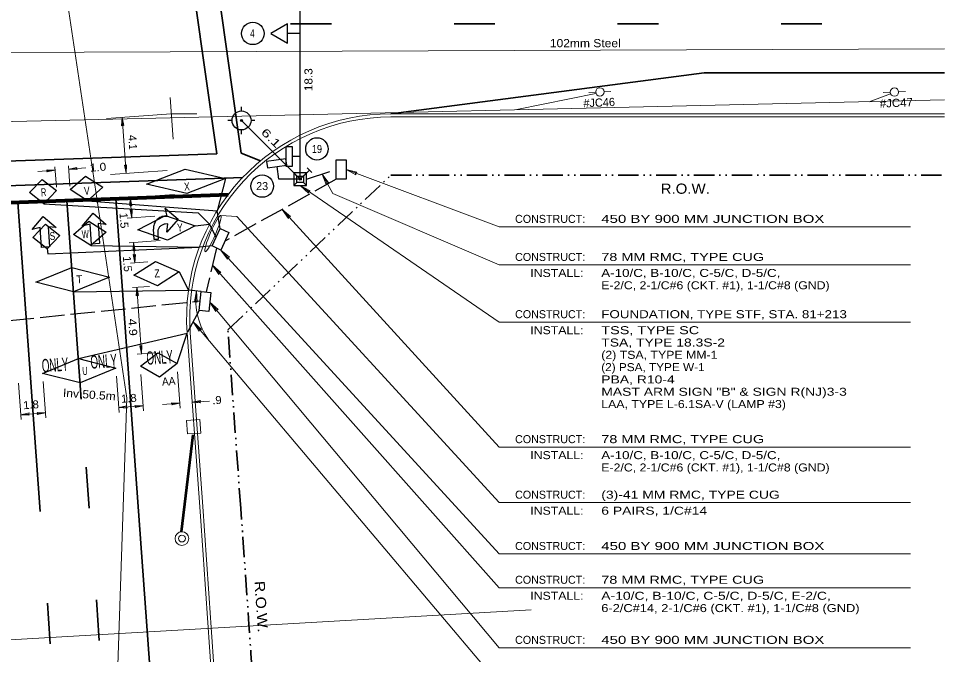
# Model space of a CAD drawing. Extents: x 168203 to 169864, y 223196 to 223870.
# Drawn here: x 168359.5 to 168427.5, y 223579 to 223625.7 of the extents above; entities that cross this region are included whole.
import ezdxf
from ezdxf.enums import TextEntityAlignment as Align

# ---------------------------------------------------------------- set-up
doc = ezdxf.new("R2010")
doc.units = 0
doc.header["$LTSCALE"] = 0.3
doc.header["$PDMODE"] = 32
doc.header["$PDSIZE"] = 0.15
for name, pattern in [('DASH_DOUBLE_DOT', [9.2, 5, -1.2, 0.3, -1.2, 0.3, -1.2]), ('LONG_DASH_SHORT_DASH', [9.9, 6, -1.2, 1.5, -1.2]), ('LONG_DASHED', [7.5, 6, -1.5])]:
    doc.linetypes.add(name, pattern=pattern)
for name, color, linetype, lineweight in [('1', 7, 'Continuous', 13), ('10', 7, 'Continuous', 13), ('23', 7, 'Continuous', 25), ('32', 7, 'Continuous', 25), ('36', 7, 'Continuous', 35), ('4', 7, 'Continuous', 25), ('6', 7, 'Continuous', 25), ('8', 7, 'Continuous', 25)]:
    doc.layers.add(name, color=color, linetype=linetype, lineweight=lineweight)

msp = doc.modelspace()

# ---------------------------------------------------------------- linework, layer by layer
at = {"layer": '1'}
for p, q in [((168386.8184, 223618.6676), (168427.4519, 223618.6676)), ((168386.8186, 223618.4376), (168427.4519, 223618.4376)), ((168372.8042, 223589.4862), (168371.8575, 223602.5864)), ((168373.0337, 223589.5027), (168372.087, 223602.6029))]:
    msp.add_line(p, q, dxfattribs=at)
at = {"layer": '1', "linetype": 'DASH_DOUBLE_DOT', "lineweight": 35}
msp.add_lwpolyline([(168375.797, 223589.7022), (168374.8503, 223602.8023), (168386.819, 223614.1674), (168427.4519, 223614.1674)], dxfattribs=at)
at = {"layer": '1'}
msp.add_lwpolyline([(168371.8028, 223596.1717), (168372.8032, 223596.244), (168372.8755, 223595.2436), (168371.8751, 223595.1713)], close=True, dxfattribs=at)
for radius in [0.5006, 0.2503]:
    msp.add_circle((168371.4777, 223587.4961), radius, dxfattribs=at)
for centre, radius, start, end in [((168386.8184, 223603.6676), 15, 90.00005, 184.13349), ((168386.8184, 223603.6676), 14.77, 90.00005, 184.13349), ((166159.6759, 223429.5469), 2218.9, 3.25121, 4.13349), ((166159.6759, 223429.5469), 2219.13, 3.2513, 4.13349)]:
    msp.add_arc(centre, radius, start, end, dxfattribs=at)
at = {"layer": '1', "linetype": 'DASH_DOUBLE_DOT', "lineweight": 35}
msp.add_arc((166159.6764, 223429.5467), 2221.9, 3.2524, 4.13349, dxfattribs=at)
at = {"layer": '10'}
for p, q in [((168383.5228, 223614.577), (168394.7583, 223610.3737)), ((168380.1569, 223613.3977), (168394.7583, 223603.38)), ((168378.8295, 223611.6525), (168394.7583, 223594.2099)), ((168424.9661, 223610.3737), (168394.7583, 223610.3737)), ((168374.3439, 223608.6723), (168394.7583, 223586.3688)), ((168373.7185, 223607.5532), (168394.7583, 223583.8912)), ((168424.9661, 223607.5799), (168394.7583, 223607.5799)), ((168373.532, 223604.8544), (168394.7583, 223579.4795)), ((168372.3015, 223603.4006), (168394.7583, 223576.8324)), ((168424.9661, 223603.38), (168394.7583, 223603.38)), ((168424.9661, 223594.2099), (168394.7583, 223594.2099)), ((168424.9661, 223590.1343), (168394.7583, 223590.1343)), ((168424.9661, 223586.3688), (168394.7583, 223586.3688)), ((168424.9661, 223583.8912), (168394.7583, 223583.8912)), ((168424.9661, 223579.4795), (168394.7583, 223579.4795))]:
    msp.add_line(p, q, dxfattribs=at)
for points in [[(168381.7597, 223614.2359), (168382.5581, 223612.8193), (168394.7583, 223607.5799)], [(168374.3369, 223611.2068), (168375.516, 223611.1213), (168394.7583, 223590.1343)]]:
    msp.add_lwpolyline(points, dxfattribs=at)
for points in [[(168382.0724, 223613.4786), (168381.7597, 223614.2359), (168382.2535, 223613.5806), (168382.1191, 223613.5983)], [(168384.2497, 223614.1989), (168383.5228, 223614.577), (168384.3225, 223614.3936), (168384.2083, 223614.3205)], [(168380.7713, 223612.8556), (168380.1569, 223613.3977), (168380.8889, 223613.027), (168380.7604, 223612.9836)], [(168379.3045, 223610.9849), (168378.8295, 223611.6525), (168379.458, 223611.125), (168379.323, 223611.112)], [(168374.8197, 223608.0053), (168374.3439, 223608.6723), (168374.973, 223608.1456), (168374.8381, 223608.1324)], [(168374.1846, 223606.8794), (168373.7185, 223607.5532), (168374.3399, 223607.0175), (168374.2048, 223607.0063)], [(168372.4, 223604.8619), (168372.5366, 223605.6698), (168372.6075, 223604.8524), (168372.503, 223604.9387)], [(168373.9776, 223604.1668), (168373.532, 223604.8544), (168374.137, 223604.3001), (168374.0016, 223604.293)], [(168372.7506, 223602.7153), (168372.3015, 223603.4006), (168372.9093, 223602.8494), (168372.774, 223602.8416)]]:
    msp.add_lwpolyline(points, close=True, dxfattribs=at)
msp.add_arc((168377.6877, 223605.0331), 5.1904, 172.95283, 214.81687, dxfattribs=at)
msp.add_ellipse((168373.7576, 223609.8746), major_axis=(0.5793, 1.3322), ratio=0.131884, dxfattribs=at)
at = {"layer": '23', "lineweight": 13}
for p, q in [((168359.4003, 223651.3453), (168367.4305, 223597.8004)), ((168298.0362, 223622.959), (168427.4519, 223623.4301)), ((168401.8482, 223620.2582), (168401.3488, 223620.2355)), ((168402.4726, 223620.2866), (168402.9721, 223620.3093)), ((168424.0846, 223620.2776), (168424.584, 223620.3002)), ((168339.1201, 223617.6451), (168427.4519, 223619.7026)), ((168401.8692, 223620.1495), (168396.0557, 223618.9857)), ((168421.9274, 223619.5562), (168423.4911, 223620.1452)), ((168423.4601, 223620.2491), (168422.9607, 223620.2265)), ((168367.4305, 223597.8004), (168365.9593, 223554.7364)), ((168353.4742, 223579.7703), (168397.1161, 223582.2547))]:
    msp.add_line(p, q, dxfattribs=at)
at = {"layer": '23', "lineweight": 53}
msp.add_line((168371.4416, 223587.9948), (168372.2988, 223595.0996), dxfattribs=at)
at = {"layer": '23', "lineweight": 13}
for centre in [(168402.1604, 223620.2724), (168423.7724, 223620.2634)]:
    msp.add_circle(centre, 0.3125, dxfattribs=at)
at = {"layer": '32'}
for p, q in [((168380.1659, 223624.5676), (168379.2261, 223624.5676)), ((168375.8525, 223618.181), (168380.1659, 223613.8676)), ((168380.1659, 223615.5237), (168379.5811, 223615.5237)), ((168380.1659, 223613.8676), (168380.1659, 223615.5237)), ((168378.5896, 223613.8676), (168378.4584, 223614.7982)), ((168380.1659, 223613.8676), (168380.8304, 223614.5321)), ((168380.6643, 223614.6982), (168381.003, 223614.3596)), ((168380.1659, 223613.8676), (168378.5896, 223613.8676))]:
    msp.add_line(p, q, dxfattribs=at)
msp.add_lwpolyline([(168380.1659, 223613.8676), (168380.1659, 223632.1676), (168381.1057, 223632.1676)], dxfattribs=at)
for points in [[(168378.0063, 223624.5495), (168379.2261, 223623.8628), (168379.2261, 223624.5676), (168379.2261, 223625.2724)], [(168379.1113, 223616.2331), (168379.1113, 223614.8144), (168379.5811, 223614.8144), (168379.5811, 223616.2331)], [(168379.0997, 223615.3631), (168377.6949, 223615.165), (168377.7605, 223614.6998), (168379.1653, 223614.8979)]]:
    msp.add_lwpolyline(points, close=True, dxfattribs=at)
for centre in [(168376.6839, 223624.5665), (168381.3874, 223616.0869), (168377.3653, 223613.3642)]:
    msp.add_circle(centre, 0.8236, dxfattribs=at)
at = {"layer": '36'}
for p, q in [((168374.0279, 223615.7265), (168368.7066, 223653.4676)), ((168375.8367, 223615.7899), (168370.5243, 223653.4676)), ((168379.4521, 223625.2671), (168382.4522, 223625.2671)), ((168391.4522, 223625.2671), (168394.4522, 223625.2671)), ((168403.4522, 223625.2671), (168406.4522, 223625.2671)), ((168415.4522, 223625.2671), (168418.4522, 223625.2671)), ((168409.8188, 223621.667), (168386.8189, 223618.6672)), ((168409.8188, 223621.667), (168427.4519, 223621.667)), ((168374.0279, 223615.7265), (168342.9941, 223614.6383)), ((168375.8367, 223615.7899), (168377.2549, 223615.2235)), ((168375.9373, 223613.9924), (168343.1786, 223612.8438)), ((168361.075, 223589.4767), (168359.4361, 223612.1546)), ((168364.0889, 223597.7154), (168363.0357, 223612.2892)), ((168369.3895, 223574.3146), (168366.6354, 223612.4238)), ((168364.6656, 223589.7363), (168364.4493, 223592.7284))]:
    msp.add_line(p, q, dxfattribs=at)
at = {"layer": '36', "lineweight": 80}
msp.add_line((168374.8667, 223612.7316), (168351.8768, 223611.872), dxfattribs=at)
at = {"layer": '36', "linetype": 'LONG_DASH_SHORT_DASH', "lineweight": 25}
for points in [[(168370.1991, 223611.1514), (168370.3937, 223611.1655), (168370.2543, 223611.7421), (168371.1931, 223610.9299), (168370.3809, 223609.9911), (168370.4359, 223610.5818), (168370.2413, 223610.5677)], [(168369.6998, 223609.9419), (168369.735, 223609.4554), (168369.4432, 223609.4344), (168369.3869, 223610.2126)]]:
    msp.add_lwpolyline(points, dxfattribs=at)
for points in [[(168360.4884, 223610.1864), (168361.3006, 223611.1252), (168362.2394, 223610.313), (168361.6487, 223610.368), (168361.7542, 223608.9088), (168361.1705, 223608.8666), (168361.065, 223610.3258)], [(168364.161, 223610.4278), (168364.9732, 223611.3666), (168365.912, 223610.5544), (168365.3213, 223610.6094), (168365.4268, 223609.1502), (168364.8431, 223609.108), (168364.7376, 223610.5672)]]:
    msp.add_lwpolyline(points, close=True, dxfattribs=at)
for centre, radius in [((168370.2625, 223610.2759), 0.8778), ((168370.2836, 223609.984), 0.5852)]:
    msp.add_arc(centre, radius, 94.13419, 184.13419, dxfattribs=at)
at = {"layer": '36'}
for radius in [2210.8499, 2207.2499]:
    msp.add_arc((166159.6765, 223429.5465), radius, 3.90229, 3.98029, dxfattribs=at)
at = {"layer": '4'}
for p, q in [((168379.687, 223614.3375), (168379.922, 223614.1025)), ((168380.6268, 223614.3375), (168380.3918, 223614.1025)), ((168379.687, 223613.3977), (168379.922, 223613.6327)), ((168380.6268, 223613.3977), (168380.3918, 223613.6327))]:
    msp.add_line(p, q, dxfattribs=at)
for points in [[(168379.687, 223614.3375), (168379.687, 223613.3977), (168380.6268, 223613.3977), (168380.6268, 223614.3375)], [(168379.922, 223614.1025), (168380.3918, 223614.1025), (168380.3918, 223613.6327), (168379.922, 223613.6327)]]:
    msp.add_lwpolyline(points, close=True, dxfattribs=at)
msp.add_point((168380.1659, 223613.8676), dxfattribs=at)
at = {"layer": '6', "lineweight": 13}
for p, q in [((168370.6083, 223619.8702), (168370.8302, 223616.8016)), ((168367.3795, 223614.2995), (168367.0826, 223618.4067)), ((168363.2591, 223613.3618), (168363.1512, 223614.8548)), ((168360.9109, 223614.4364), (168362.1718, 223614.5275)), ((168362.2612, 223613.2897), (168362.1533, 223614.7827)), ((168363.1697, 223614.5997), (168364.4306, 223614.6908)), ((168366.2301, 223614.2163), (168370.4036, 223614.518)), ((168367.361, 223612.4932), (168370.9243, 223612.7508)), ((168367.7911, 223611.0204), (168367.683, 223612.5165)), ((168367.4691, 223610.9971), (168369.4965, 223611.1436)), ((168367.5988, 223609.2017), (168369.8737, 223609.3661)), ((168368.0289, 223607.7289), (168367.9208, 223609.225)), ((168367.7069, 223607.7056), (168368.9653, 223607.7965)), ((168367.8366, 223605.9102), (168369.0951, 223606.0012)), ((168368.512, 223601.0463), (168368.1587, 223605.9335)), ((168368.1897, 223601.023), (168369.5353, 223601.1203)), ((168366.8668, 223596.7466), (168366.6744, 223599.409)), ((168368.6608, 223596.8763), (168368.4684, 223599.5386)), ((168371.3538, 223597.071), (168371.1614, 223599.7335)), ((168359.6848, 223596.2275), (168359.4924, 223598.89)), ((168361.4801, 223596.3573), (168361.2877, 223599.0197)), ((168366.8408, 223597.1072), (168368.6347, 223597.2368)), ((168370.061, 223597.34), (168371.3278, 223597.4315)), ((168372.2253, 223597.4963), (168373.4921, 223597.5878)), ((168359.6588, 223596.5883), (168361.4541, 223596.718))]:
    msp.add_line(p, q, dxfattribs=at)
at = {"layer": '6', "linetype": 'LONG_DASHED'}
for p, q in [((168380.6268, 223613.8676), (168382.809, 223614.577)), ((168382.809, 223613.8676), (168374.6364, 223609.3186)), ((168374.2786, 223610.2591), (168374.0555, 223611.5484)), ((168373.9861, 223609.6129), (168373.5048, 223610.5775)), ((168373.6936, 223608.9667), (168372.7546, 223608.8838)), ((168374.0188, 223608.8195), (168373.255, 223605.5986)), ((168372.9002, 223605.6377), (168371.9596, 223605.7208)), ((168343.1548, 223601.8824), (168372.8225, 223604.9326)), ((168372.7449, 223604.2276), (168371.8584, 223602.574))]:
    msp.add_line(p, q, dxfattribs=at)
at = {"layer": '6'}
for p, q in [((168374.6687, 223613.924), (168374.0555, 223611.5484)), ((168364.5397, 223612.2894), (168374.0555, 223611.5484)), ((168372.4395, 223610.4541), (168373.5048, 223610.5775)), ((168364.778, 223608.9978), (168372.7546, 223608.8838)), ((168371.2846, 223607.0618), (168371.9596, 223605.7208)), ((168363.5197, 223605.5982), (168371.9596, 223605.7208)), ((168363.8729, 223600.7109), (168371.8584, 223602.574)), ((168371.1181, 223600.3323), (168371.8584, 223602.574))]:
    msp.add_line(p, q, dxfattribs=at)
at = {"layer": '6', "lineweight": 13}
msp.add_lwpolyline([(168365.9333, 223618.3234), (168370.6953, 223618.6676), (168372.5686, 223618.6676)], dxfattribs=at)
for points in [[(168367.0522, 223617.793), (168367.0826, 223618.4067), (168367.2076, 223617.8042), (168367.1221, 223617.8592)], [(168367.4099, 223614.9132), (168367.3795, 223614.2995), (168367.2545, 223614.902), (168367.34, 223614.847)], [(168361.5581, 223614.5579), (168362.1718, 223614.5275), (168361.5693, 223614.4025), (168361.6243, 223614.488)], [(168363.7834, 223614.5693), (168363.1697, 223614.5997), (168363.7722, 223614.7247), (168363.7172, 223614.6392)], [(168367.6526, 223611.9028), (168367.683, 223612.5165), (168367.808, 223611.914), (168367.7225, 223611.969)], [(168367.8215, 223611.6341), (168367.7911, 223611.0204), (168367.6661, 223611.6229), (168367.7516, 223611.5679)], [(168367.8904, 223608.6113), (168367.9208, 223609.225), (168368.0458, 223608.6225), (168367.9603, 223608.6775)], [(168368.0593, 223608.3426), (168368.0289, 223607.7289), (168367.9039, 223608.3314), (168367.9894, 223608.2764)], [(168368.1283, 223605.3198), (168368.1587, 223605.9335), (168368.2837, 223605.331), (168368.1982, 223605.386)], [(168368.5424, 223601.66), (168368.512, 223601.0463), (168368.387, 223601.6488), (168368.4725, 223601.5938)], [(168367.4545, 223597.0768), (168366.8408, 223597.1072), (168367.4433, 223597.2322), (168367.3883, 223597.1467)], [(168368.021, 223597.2672), (168368.6347, 223597.2368), (168368.0322, 223597.1118), (168368.0872, 223597.1973)], [(168370.7141, 223597.4619), (168371.3278, 223597.4315), (168370.7253, 223597.3065), (168370.7803, 223597.392)], [(168372.8391, 223597.4659), (168372.2254, 223597.4963), (168372.8279, 223597.6213), (168372.7729, 223597.5358)], [(168360.2725, 223596.5579), (168359.6588, 223596.5883), (168360.2613, 223596.7133), (168360.2063, 223596.6278)], [(168360.8404, 223596.7484), (168361.4541, 223596.718), (168360.8516, 223596.593), (168360.9066, 223596.6785)]]:
    msp.add_lwpolyline(points, close=True, dxfattribs=at)
at = {"layer": '6'}
for points in [[(168383.5228, 223613.8676), (168382.809, 223613.8676), (168382.809, 223615.2863), (168383.5228, 223615.2863)], [(168368.8838, 223613.5057), (168371.7114, 223614.6124), (168374.6687, 223613.924), (168371.8412, 223612.817)], [(168360.2854, 223612.8843), (168361.2179, 223613.8541), (168362.2801, 223613.0285), (168361.3477, 223612.0587)], [(168363.278, 223613.1006), (168364.41, 223614.0847), (168365.6717, 223613.2736), (168364.5397, 223612.2894)], [(168363.5163, 223609.809), (168364.6483, 223610.7931), (168365.91, 223609.982), (168364.778, 223608.9978)], [(168368.2505, 223610.1512), (168370.2801, 223611.2002), (168372.4395, 223610.4541), (168370.4099, 223609.4048)], [(168360.5234, 223609.5928), (168361.4559, 223610.5626), (168362.5181, 223609.737), (168361.5857, 223608.7672)], [(168374.3439, 223608.6723), (168373.6936, 223608.9667), (168374.2786, 223610.2591), (168374.9289, 223609.9648)], [(168360.7615, 223606.3013), (168363.3899, 223607.3936), (168366.1481, 223606.6906), (168363.5197, 223605.5982)], [(168367.9433, 223606.8202), (168369.549, 223607.8387), (168371.2846, 223607.0618), (168369.6788, 223606.0433)], [(168373.4544, 223604.1494), (168372.7449, 223604.2276), (168372.9002, 223605.6377), (168373.6097, 223605.5595)], [(168361.2445, 223599.6186), (168363.8729, 223600.7109), (168366.6311, 223600.0079), (168364.0027, 223598.9155)], [(168368.4251, 223600.1376), (168369.7067, 223601.1326), (168371.1181, 223600.3323), (168369.8365, 223599.3372)]]:
    msp.add_lwpolyline(points, close=True, dxfattribs=at)
for points in [[(168361.3477, 223612.0587), (168372.6735, 223611.4071), (168373.5048, 223610.5775)], [(168361.5857, 223608.7672), (168361.6249, 223608.3837), (168372.7546, 223608.8838)]]:
    msp.add_lwpolyline(points, dxfattribs=at)
at = {"layer": '8'}
for p, q in [((168375.8493, 223618.8807), (168375.8429, 223619.1681)), ((168375.1593, 223618.165), (168374.8461, 223618.1714)), ((168376.8396, 223618.1714), (168376.5521, 223618.165)), ((168375.8493, 223617.1682), (168375.8493, 223617.4877))]:
    msp.add_line(p, q, dxfattribs=at)
msp.add_circle((168375.8525, 223618.181), 0.6965, dxfattribs=at)
msp.add_point((168375.8493, 223618.1778), dxfattribs=at)

# ---------------------------------------------------------------- texts
at = {"layer": '1', "width": 1.1}
msp.add_text('R.O.W.', height=0.7499, dxfattribs=at).set_placement((168408.423, 223612.7975), align=Align.CENTER)
at = {"layer": '1', "width": 1.15}
msp.add_text('R.O.W.', height=0.7499, rotation=273.946, dxfattribs=at).set_placement((168376.9287, 223582.4755), align=Align.CENTER)
at = {"layer": '10'}
for p in [(168395.933, 223610.6629), (168395.933, 223607.8691), (168395.933, 223603.6692), (168395.933, 223594.4991), (168395.933, 223590.4235), (168395.933, 223586.658), (168395.933, 223584.1804), (168395.933, 223579.7687)]:
    msp.add_text('CONSTRUCT:', height=0.5873, dxfattribs=at).set_placement(p)
for s, width, p in [('450 BY 900 MM JUNCTION BOX           ', 1.4, (168402.2583, 223610.6629)), ('78 MM RMC, TYPE CUG                  ', 1.35, (168402.2583, 223607.8691)), ('A-10/C, B-10/C, C-5/C, D-5/C,', 1.25, (168402.2583, 223606.6944)), ('E-2/C, 2-1/C#6 (CKT. #1), 1-1/C#8 (GND)       ', 1.15, (168402.2583, 223605.7907)), ('FOUNDATION, TYPE STF, STA. 81+213    ', 1.25, (168402.2583, 223603.6692)), ('TSS, TYPE SC                         ', 1.35, (168402.2583, 223602.4945)), ('TSA, TYPE 18.3S-2                    ', 1.3, (168402.2583, 223601.5908)), ('(2) TSA, TYPE MM-1                   ', 1.15, (168402.2583, 223600.6872)), ('(2) PSA, TYPE W-1                    ', 1.1, (168402.2583, 223599.7836)), ('PBA, R10-4                           ', 1.3, (168402.2583, 223598.88)), ('MAST ARM SIGN "B" & SIGN R(NJ)3-3    ', 1.3, (168402.2583, 223597.9764)), ('LAA, TYPE L-6.1SA-V (LAMP #3)         ', 1.15, (168402.2583, 223597.0728)), ('78 MM RMC, TYPE CUG                  ', 1.35, (168402.2583, 223594.4991)), ('A-10/C, B-10/C, C-5/C, D-5/C,', 1.25, (168402.2583, 223593.3244)), ('E-2/C, 2-1/C#6 (CKT. #1), 1-1/C#8 (GND)       ', 1.15, (168402.2583, 223592.4207)), ('(3)-41 MM RMC, TYPE CUG              ', 1.3, (168402.2583, 223590.4235)), ('6 PAIRS, 1/C#14                      ', 1.3, (168402.2583, 223589.2488)), ('450 BY 900 MM JUNCTION BOX           ', 1.4, (168402.2583, 223586.658)), ('78 MM RMC, TYPE CUG                  ', 1.35, (168402.2583, 223584.1804)), ('A-10/C, B-10/C, C-5/C, D-5/C, E-2/C, ', 1.3, (168402.2583, 223583.0057)), ('6-2/C#14, 2-1/C#6 (CKT. #1), 1-1/C#8 (GND) ', 1.2, (168402.2583, 223582.102)), ('450 BY 900 MM JUNCTION BOX           ', 1.4, (168402.2583, 223579.7687))]:
    msp.add_text(s, height=0.5873, dxfattribs=dict(at, width=width)).set_placement(p)
at = {"layer": '10', "width": 1.15}
for p in [(168400.9602, 223606.6944), (168400.9602, 223602.4945), (168400.9602, 223593.3244), (168400.9602, 223589.2488), (168400.9602, 223583.0057)]:
    msp.add_text('INSTALL:', height=0.5873, dxfattribs=at).set_placement(p, align=Align.RIGHT)
at = {"layer": '23', "width": 1.1}
msp.add_text('102mm Steel', height=0.6, dxfattribs=at).set_placement((168401.0861, 223623.5526), align=Align.CENTER)
at = {"layer": '23'}
msp.add_text('#JC46', height=0.6, rotation=2.6, dxfattribs=at).set_placement((168402.1178, 223619.1921), align=Align.CENTER)
for s, rotation, width, p in [('#JC47', 2.6, 1.05, (168423.9303, 223619.1693)), ('Inv.50.5m', 356.065, 1.1, (168364.6616, 223597.7677))]:
    msp.add_text(s, height=0.6, rotation=rotation, dxfattribs=dict(at, width=width)).set_placement(p, align=Align.CENTER)
at = {"layer": '32'}
for s, width, p in [('4', 0.75, (168376.6455, 223624.2729)), ('19', 0.85, (168381.3875, 223615.7933))]:
    msp.add_text(s, height=0.5873, dxfattribs=dict(at, width=width)).set_placement(p, align=Align.CENTER)
for s, rotation, width, p in [('18.3', 90, 1.1, (168381.0585, 223621.1703)), ('6.1', 315, 1.5, (168377.8158, 223616.6866))]:
    msp.add_text(s, height=0.5873, rotation=rotation, dxfattribs=dict(at, width=width)).set_placement(p, align=Align.CENTER)
msp.add_text('23', height=0.5873, dxfattribs=at).set_placement((168377.3654, 223613.0706), align=Align.CENTER)
at = {"layer": '36', "width": 0.55}
for p in [(168369.8758, 223600.3124), (168362.1961, 223599.756), (168365.7648, 223600.0223)]:
    msp.add_text('ONLY', height=0.9715, rotation=3.898, dxfattribs=at).set_placement(p, align=Align.CENTER)
at = {"layer": '6'}
msp.add_text('4.1', height=0.5873, rotation=274.133, dxfattribs=at).set_placement((168367.5738, 223616.5531), align=Align.CENTER)
for s, rotation, width, p in [('1.0', 4.132, 1.1, (168365.3365, 223614.4585)), ('X', 4.134, 0.8, (168371.8625, 223613.0352)), ('R', 4.134, 0.7, (168361.3462, 223612.6163)), ('V', 4.134, 0.8, (168364.5164, 223612.732)), ('1.5', 274.133, 1.05, (168366.9345, 223610.8149)), ('W', 4.134, 0.65, (168364.406, 223609.5428)), ('Y', 4.134, 0.8, (168371.3534, 223610.0309)), ('S', 4.134, 0.75, (168361.9916, 223609.4077)), ('1.5', 274.133, 1.05, (168367.1847, 223607.626)), ('T', 4.134, 0.9, (168363.9699, 223606.231)), ('Z', 4.134, 0.85, (168369.6738, 223606.6639)), ('4.9', 274.135, 1.15, (168367.5789, 223602.9845)), ('U', 4.134, 0.7, (168364.3782, 223599.505)), ('AA', 4.134, 0.95, (168370.5259, 223598.7489)), ('1.8', 4.134, 1.05, (168367.5998, 223597.4993)), ('.9', 4.134, 1.05, (168374.0649, 223597.3638)), ('1.8', 4.134, 1.05, (168360.4197, 223597.0263))]:
    msp.add_text(s, height=0.5873, rotation=rotation, dxfattribs=dict(at, width=width)).set_placement(p, align=Align.CENTER)

doc.saveas('drawing.dxf')
